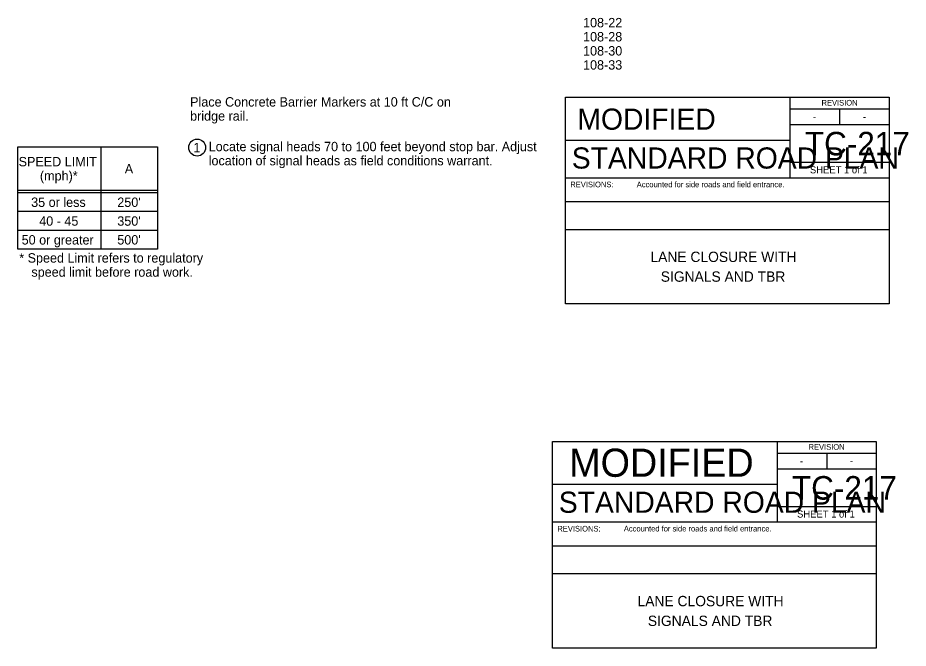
# Model space of a CAD drawing. Extents: x 10133 to 81668, y 4692 to 11018.
# Drawn here: x 22215 to 24108, y 4692 to 6033 of the extents above; entities that cross this region are included whole.
import ezdxf

# ---------------------------------------------------------------- set-up
doc = ezdxf.new("R2010")
doc.units = 0
for name, color, linetype in [('Cell', 7, 'Continuous'), ('dsnCellElements', 7, 'Continuous'), ('dsnCellsNorthArrow', 7, 'Continuous'), ('DsnShtRevisedText', 7, 'Continuous'), ('dsnStdBlockModified', 7, 'Continuous'), ('dsnTextFinalPlan', 7, 'Continuous'), ('Level 6', 7, 'Continuous'), ('SheetBorder', 7, 'Continuous')]:
    doc.layers.add(name, color=color, linetype=linetype)

msp = doc.modelspace()

# ---------------------------------------------------------------- linework, layer by layer
at = {"layer": 'dsnCellElements'}
msp.add_circle((22596.2, 5756.7), 18, dxfattribs=at)
at = {"layer": 'dsnTextFinalPlan'}
for p, q in [((23856.6, 5864), (23856.6, 5772.7)), ((23856.6, 5839.1), (24067.5, 5839.1)), ((23962.1, 5839.1), (23962.1, 5805.9)), ((23856.6, 5805.9), (24067.5, 5805.9)), ((23379.5, 5772.7), (23856.6, 5772.7)), ((23856.6, 5772.7), (23856.6, 5692.7)), ((24067.5, 5724.9), (23856.6, 5724.9)), ((23379.5, 5692.7), (24067.5, 5692.7)), ((23379.5, 5641.7), (24067.5, 5641.7)), ((23379.5, 5582.7), (24067.5, 5582.7)), ((23829.1, 5131.6), (23829.1, 5040.3)), ((23829.1, 5106.7), (24040.1, 5106.7)), ((23934.6, 5106.7), (23934.6, 5073.5)), ((23829.1, 5073.5), (24040.1, 5073.5)), ((23352, 5040.3), (23829.1, 5040.3)), ((23829.1, 5040.3), (23829.1, 4960.3)), ((24040.1, 4992.5), (23829.1, 4992.5)), ((23352, 4960.3), (24040.1, 4960.3)), ((23352, 4909.3), (24040.1, 4909.3)), ((23352, 4850.3), (24040.1, 4850.3))]:
    msp.add_line(p, q, dxfattribs=at)
for points in [[(23379.5, 5864), (24067.5, 5864), (24067.5, 5424), (23379.5, 5424)], [(23352, 5131.6), (24040.1, 5131.6), (24040.1, 4691.6), (23352, 4691.6)]]:
    msp.add_lwpolyline(points, close=True, dxfattribs=at)
at = {"layer": 'Level 6'}
for p, q in [((22214.9, 5758.1), (22511.7, 5758.1)), ((22214.9, 5540.5), (22214.9, 5758.1)), ((22391.7, 5758.1), (22391.7, 5540.5)), ((22511.7, 5758.1), (22511.7, 5540.5)), ((22511.7, 5665.5), (22214.9, 5665.5)), ((22511.7, 5660.5), (22214.9, 5660.5)), ((22511.7, 5620.5), (22214.9, 5620.5)), ((22511.7, 5580.5), (22214.9, 5580.5)), ((22511.7, 5540.5), (22214.9, 5540.5))]:
    msp.add_line(p, q, dxfattribs=at)

# ---------------------------------------------------------------- texts
at = {"layer": 'Cell'}
msp.add_text('REVISIONS:', height=12, dxfattribs=at).set_placement((23362, 4939.9))
at = {"layer": 'dsnCellElements'}
for s, p in [('1', (22588.1, 5746.7)), ('Locate signal heads 70 to 100 feet beyond stop bar. Adjust ', (22620.7, 5749)), ('location of signal heads as field conditions warrant.', (22620.7, 5719))]:
    msp.add_text(s, height=20, dxfattribs=at).set_placement(p)
at = {"layer": 'dsnCellsNorthArrow'}
for s, p in [('     108-22', (23379.5, 6012.6)), ('     108-28', (23379.5, 5982.6)), ('     108-30', (23379.5, 5952.6)), ('     108-33', (23379.5, 5922.6)), ('Place Concrete Barrier Markers at 10 ft C/C on ', (22581.2, 5844)), ('bridge rail.', (22581.2, 5814))]:
    msp.add_text(s, height=20, dxfattribs=at).set_placement(p)
at = {"layer": 'DsnShtRevisedText'}
for s, p in [('A', (22442.3, 5701.8)), ('35 or less', (22243.3, 5630.5)), ("250'", (22426.4, 5630.5)), ('40 - 45', (22260.4, 5590.5)), ("350'", (22426.4, 5590.5)), ('50 or greater', (22223.1, 5550.5)), ("500'", (22426.4, 5550.5))]:
    msp.add_text(s, height=20, dxfattribs=at).set_placement(p)
at = {"layer": 'dsnStdBlockModified'}
for s, height, p in [('MODIFIED', 45, (23404.6, 5794.8)), ('REVISIONS:', 12, (23389.5, 5672.3))]:
    msp.add_text(s, height=height, dxfattribs=at).set_placement(p)
at = {"layer": 'dsnTextFinalPlan'}
for s, height, p in [('REVISION', 12, (23923.6, 5846.2)), ('-', 15, (23905.1, 5814.7)), ('-', 15, (24011.6, 5815.1)), ('TC-217', 50, (23888.3, 5740.2)), ('STANDARD ROAD PLAN', 45.001, (23392.6, 5712.1)), ('SHEET 1 of 1', 15, (23899, 5702)), ('Accounted for side roads and field entrance.', 12, (23530.8, 5672.3)), ('LANE CLOSURE WITH', 22, (23559.9, 5513.3)), ('SIGNALS AND TBR', 22, (23581.8, 5471.3)), ('REVISION', 12, (23896.1, 5113.8)), ('-', 15, (23877.6, 5082.3)), ('-', 15, (23984.2, 5082.7)), ('TC-217', 50, (23860.8, 5007.8)), ('STANDARD ROAD PLAN', 45.001, (23365.1, 4979.7)), ('SHEET 1 of 1', 15, (23871.6, 4969.6)), ('Accounted for side roads and field entrance.', 12, (23503.4, 4940)), ('LANE CLOSURE WITH', 22, (23532.4, 4780.9)), ('SIGNALS AND TBR', 22, (23554.4, 4738.9))]:
    msp.add_text(s, height=height, dxfattribs=at).set_placement(p)
at = {"layer": 'Level 6'}
for s, p in [('SPEED LIMIT', (22216.6, 5716.8)), ('(mph)*', (22261.9, 5686.8)), ('* Speed Limit refers to regulatory ', (22217.9, 5512)), ('speed limit before road work.', (22243.8, 5482))]:
    msp.add_text(s, height=20, dxfattribs=at).set_placement(p)
at = {"layer": 'SheetBorder'}
msp.add_text('MODIFIED', height=60, dxfattribs=at).set_placement((23387.1, 5056.3))

doc.saveas('drawing.dxf')
